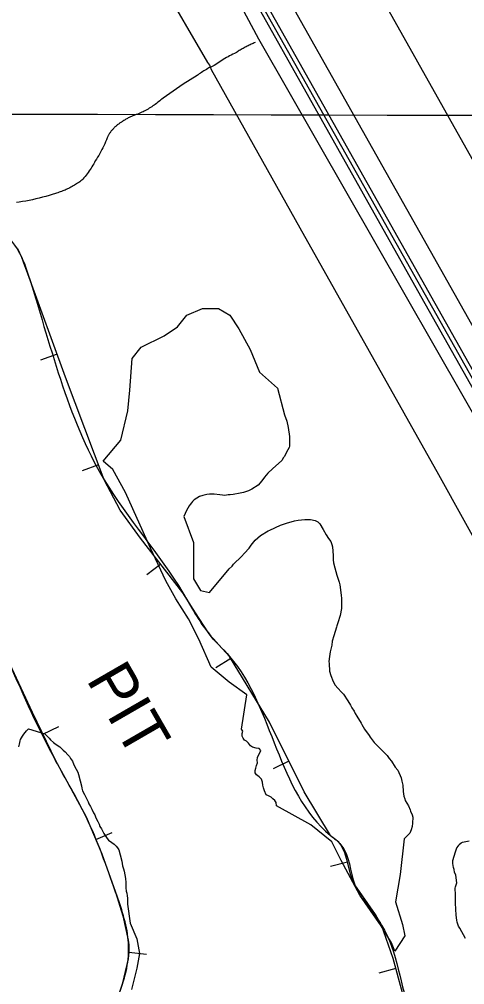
# Model space of a CAD drawing. Extents: x 3177185 to 3215018, y 812988 to 838321.
# Drawn here: x 3192464 to 3193094, y 823203 to 824566 of the extents above; entities that cross this region are included whole.
import ezdxf

# ---------------------------------------------------------------- set-up
doc = ezdxf.new("R2010")
doc.units = 0
for name, color, linetype in [('V-BORW-IDEN', 7, 'Continuous'), ('V-BORW-LINE', 7, 'Continuous'), ('V-GRID-MAJR', 7, 'Continuous'), ('V-LEVE-TOET', 7, 'Continuous'), ('V-RAIL-TRAK', 7, 'Continuous'), ('V-ROAD-CNTR', 7, 'Continuous'), ('V-SITE-VEGE', 7, 'Continuous'), ('V-SURV-LINE', 7, 'Continuous'), ('V-TOPO-SHOR', 7, 'Continuous')]:
    doc.layers.add(name, color=color, linetype=linetype)

msp = doc.modelspace()

# ---------------------------------------------------------------- linework, layer by layer
at = {"layer": 'V-BORW-LINE'}
for p, q in [((3192517.991, 824093.435), (3192494.512, 824084.848)), ((3192576.349, 823937.392), (3192552.949, 823928.591)), ((3192664.126, 823796.922), (3192644.37, 823781.6020000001)), ((3192763.312, 823663.634), (3192741.9620000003, 823650.628)), ((3192497.732, 823556.731), (3192520.272, 823567.547)), ((3192845.395, 823518.821), (3192823.012, 823507.685)), ((3192572.419, 823407.936), (3192595.392, 823417.797)), ((3192928.254, 823376.17), (3192904.069, 823369.841)), ((3192619.248, 823248.904), (3192644.08, 823246.006)), ((3192996.52, 823225.963), (3192972.395, 823219.404))]:
    msp.add_line(p, q, dxfattribs=at)
for points in [[(3193005.934, 823191.332), (3192992.722, 823239.931), (3192976.418, 823287.094), (3192967.948, 823301.838), (3192938.651, 823343.995), (3192933.0670000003, 823357.779), (3192927.286, 823379.8690000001), (3192923.827, 823390.643), (3192918.919, 823400.677), (3192915.682, 823404.332), (3192909.56, 823408.784), (3192906.61, 823411.094), (3192904.153, 823413.796), (3192866.96, 823475.476), (3192818.068, 823573.747), (3192761.5640000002, 823666.5040000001), (3192746.238, 823682.844), (3192738.419, 823690.924), (3192731.482, 823699.6780000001), (3192713.423, 823728.017), (3192695.518, 823756.439), (3192635.544, 823833.779), (3192606.807, 823873.113), (3192584.431, 823915.904), (3192529.812, 824061.117), (3192476.548, 824206.74), (3192472.168, 824218.468), (3192467.754, 824230.1900000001), (3192462.112, 824242.243)], [(3192337.378, 823940.962), (3192394.177, 823799.838), (3192450.6750000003, 823656.781), (3192482.6950000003, 823588.069), (3192515.512, 823519.68), (3192537.107, 823479.862), (3192558.6750000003, 823439.9550000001), (3192581.161, 823387.567), (3192600.502, 823333.666), (3192610.71, 823300.028), (3192618.286, 823265.887), (3192619.163, 823259.2980000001), (3192619.292, 823249.2760000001), (3192618.13, 823239.322), (3192609.906, 823203.8520000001), (3192603.901, 823186.684)]]:
    msp.add_lwpolyline(points, dxfattribs=at)
msp.add_spline([(3192337.378, 823940.962), (3192450.6750000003, 823656.781), (3192515.512, 823519.68), (3192558.6750000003, 823439.9550000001), (3192600.502, 823333.666), (3192618.286, 823265.887), (3192618.13, 823239.322), (3192596.168, 823170.181), (3192570.128, 823124.488), (3192544.017, 823075.534), (3192525.992, 822981.143), (3192537.224, 822863.983), (3192568.707, 822741.261), (3192590.757, 822730.8420000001), (3192607.4760000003, 822734.716), (3192633.424, 822744.133), (3192790.951, 822860.632), (3192848.333, 822890.561), (3193002.452, 822993.536), (3193064.424, 823044.062), (3193073.036, 823061.536), (3193065.488, 823079.991), (3193018.025, 823160.412), (3192976.418, 823287.094), (3192938.651, 823343.995), (3192918.919, 823400.677), (3192904.153, 823413.796), (3192761.5640000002, 823666.5040000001), (3192731.482, 823699.6780000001), (3192695.518, 823756.439), (3192584.431, 823915.904), (3192476.548, 824206.74), (3192467.754, 824230.1900000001), (3192433.582, 824267.9450000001), (3192365.528, 824253.63), (3192313.008, 824232.577), (3192261.659, 824199.732), (3192232.149, 824151.405), (3192237.406, 824127.957), (3192259.282, 824060.314), (3192337.378, 823940.962)], degree=3, dxfattribs=at)
at = {"layer": 'V-GRID-MAJR'}
msp.add_spline([(3181368.912, 824461.486), (3186603.869, 824447.399), (3191838.828, 824434.0750000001), (3197073.789, 824421.511), (3202308.752, 824409.709), (3207543.717, 824398.669), (3212778.683, 824388.39), (3212778.684, 824388.39)], degree=3, dxfattribs=at)
at = {"layer": 'V-LEVE-TOET'}
for points in [[(3192443.9620000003, 825569.056), (3192576.759, 825332.2270000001), (3192715.666, 825063.0530000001), (3192905.627, 824722.775), (3193107.897, 824362.329), (3193312.2770000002, 824000.415), (3193506.598, 823644.858), (3193758.434, 823202.424)], [(3193584.328, 822982.905), (3193407.808, 823299.272), (3193245.38, 823590.751), (3193227.242, 823622.956), (3193224.488, 823626.536), (3193223.0300000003, 823629.301), (3193219.786, 823632.719), (3193193.3850000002, 823677.941), (3193057.193, 823923.224), (3192861.4, 824271.31), (3192736.054, 824495.2880000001), (3192734.436, 824499.027), (3192733.627, 824501.466), (3192730.5470000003, 824505.536), (3192598.062, 824733.751), (3192434.161, 825019.219)]]:
    msp.add_lwpolyline(points, dxfattribs=at)
at = {"layer": 'V-RAIL-TRAK'}
msp.add_lwpolyline([(3193727.307, 822943), (3193577.661, 823206.018), (3193415.878, 823494.571), (3193219.921, 823842.66), (3193027.524, 824182.939), (3192797.072, 824592.348), (3192558.2, 825016.721), (3192352.2, 825381.723), (3192184.2600000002, 825679.875), (3191974.37, 826050.574), (3191871.696, 826233.868)], dxfattribs=at)
at = {"layer": 'V-ROAD-CNTR'}
msp.add_lwpolyline([(3191892.325178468, 826207.063558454), (3193654.2206546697, 823085.5218015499)], dxfattribs=at)
at = {"layer": 'V-SITE-VEGE'}
for p, q in [((3192474.594, 823561.301), (3192477.433, 823564.13)), ((3192477.433, 823564.13), (3192500.575, 823557.324)), ((3192466.075, 823549.177), (3192468.917, 823554.029)), ((3192468.917, 823554.029), (3192470.9450000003, 823556.857)), ((3192470.9450000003, 823556.857), (3192474.594, 823561.301)), ((3192500.575, 823557.324), (3192506.529, 823551.35)), ((3192506.529, 823551.35), (3192508.5130000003, 823548.96)), ((3192463.627, 823539.066), (3192464.444, 823542.707)), ((3192464.444, 823542.707), (3192464.8540000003, 823545.134)), ((3192464.8540000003, 823545.134), (3192465.665, 823547.156)), ((3192465.665, 823547.156), (3192466.075, 823549.177)), ((3192508.5130000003, 823548.96), (3192512.482, 823544.9770000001)), ((3192512.482, 823544.9770000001), (3192516.451, 823542.185)), ((3192516.451, 823542.185), (3192521.616, 823538.9940000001)), ((3192521.616, 823538.9940000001), (3192526.378, 823534.216)), ((3192526.378, 823534.216), (3192529.157, 823531.822)), ((3192529.157, 823531.822), (3192532.727, 823527.444)), ((3192532.727, 823527.444), (3192535.109, 823525.052)), ((3192535.109, 823525.052), (3192536.694, 823522.2660000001)), ((3192536.694, 823522.2660000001), (3192539.471, 823518.682)), ((3192539.471, 823518.682), (3192541.449, 823513.509)), ((3192541.449, 823513.509), (3192544.617, 823507.142)), ((3192544.617, 823507.142), (3192546.995, 823503.161)), ((3192546.995, 823503.161), (3192548.183, 823499.581)), ((3192548.183, 823499.581), (3192550.153, 823490.8300000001)), ((3192550.153, 823490.8300000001), (3192552.127, 823483.6680000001)), ((3192552.127, 823483.6680000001), (3192552.918, 823480.485)), ((3192552.918, 823480.485), (3192553.7060000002, 823476.905)), ((3192553.7060000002, 823476.905), (3192556.4790000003, 823471.732)), ((3192556.4790000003, 823471.732), (3192559.252, 823465.762)), ((3192559.252, 823465.762), (3192561.628, 823460.9860000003)), ((3192561.628, 823460.9860000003), (3192562.818, 823458.201)), ((3192562.818, 823458.201), (3192564.798, 823454.6190000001)), ((3192564.798, 823454.6190000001), (3192566.779, 823450.638)), ((3192566.779, 823450.638), (3192569.1550000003, 823445.8640000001)), ((3192569.1550000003, 823445.8640000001), (3192571.137, 823442.677)), ((3192571.137, 823442.677), (3192572.72, 823438.702)), ((3192572.72, 823438.702), (3192575.4930000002, 823433.524)), ((3192575.4930000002, 823433.524), (3192577.078, 823429.5430000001)), ((3192577.078, 823429.5430000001), (3192578.264, 823426.363)), ((3192578.264, 823426.363), (3192580.644, 823423.1780000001)), ((3192580.644, 823423.1780000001), (3192582.227, 823419.199)), ((3192582.227, 823419.199), (3192583.812, 823416.411)), ((3192583.812, 823416.411), (3192586.5870000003, 823412.033)), ((3192586.5870000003, 823412.033), (3192588.572, 823409.643)), ((3192588.572, 823409.643), (3192590.554, 823407.253)), ((3192590.554, 823407.253), (3192595.3200000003, 823403.667)), ((3192595.3200000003, 823403.667), (3192598.4960000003, 823401.277)), ((3192598.4960000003, 823401.277), (3192601.271, 823398.485)), ((3192601.271, 823398.485), (3192603.258, 823396.095)), ((3192603.258, 823396.095), (3192604.843, 823393.31)), ((3192604.843, 823393.31), (3192606.821, 823386.5470000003)), ((3192606.821, 823386.5470000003), (3192609.187, 823377.397)), ((3192609.187, 823377.397), (3192610.366, 823370.634)), ((3192610.366, 823370.634), (3192611.552, 823366.657)), ((3192611.552, 823366.657), (3192612.341, 823363.077)), ((3192612.341, 823363.077), (3192613.524, 823358.306)), ((3192613.524, 823358.306), (3192614.311, 823353.132)), ((3192614.311, 823353.132), (3192614.698, 823347.169)), ((3192614.698, 823347.169), (3192615.0870000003, 823342.794)), ((3192615.0870000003, 823342.794), (3192615.079, 823339.611)), ((3192615.079, 823339.611), (3192615.47, 823335.2390000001)), ((3192615.47, 823335.2390000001), (3192616.259, 823332.054)), ((3192616.259, 823332.054), (3192616.65, 823328.476)), ((3192616.65, 823328.476), (3192617.44, 823325.294)), ((3192617.434, 823322.113), (3192617.424, 823316.547)), ((3192617.44, 823325.294), (3192617.434, 823322.113)), ((3192617.424, 823316.547), (3192621.0840000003, 823290.046)), ((3192621.0840000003, 823290.046), (3192630.461, 823267.524)), ((3192630.461, 823267.524), (3192634.213, 823246.88)), ((3192634.213, 823246.88), (3192630.461, 823226.238)), ((3192630.461, 823226.238), (3192622.96, 823196.21))]:
    msp.add_line(p, q, dxfattribs=at)
for points in [[(3192688.09, 824132.318), (3192700.927, 824148.373), (3192723.3910000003, 824158), (3192745.856, 824158), (3192761.9, 824148.373), (3192774.741, 824129.107), (3192790.785, 824100.214), (3192803.622, 824068.108), (3192829.294, 824045.635), (3192839.218, 824007.767)], [(3192928.701, 823603.75), (3192932.33, 823597.676), (3192934.348, 823594.028), (3192937.575, 823589.166), (3192939.187, 823585.926), (3192941.204, 823582.281), (3192947.256, 823572.154), (3192948.467, 823570.532), (3192952.096, 823563.6460000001), (3192958.9590000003, 823554.733), (3192960.169, 823552.706), (3192965.819, 823545.005), (3192983.995, 823526.764), (3192987.223, 823522.305), (3192990.455, 823518.658), (3192995.7, 823510.148), (3192999.333, 823505.692), (3193003.765, 823495.1630000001), (3193004.5700000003, 823492.732), (3193004.969, 823490.3030000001), (3193006.171, 823484.636), (3193006.966, 823475.734), (3193007.762, 823469.258), (3193008.969, 823465.207), (3193009.774, 823463.182), (3193014.2120000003, 823455.487), (3193016.628, 823449.816), (3193017.0300000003, 823447.7930000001), (3193019.448, 823442.933), (3193020.251, 823439.693), (3193020.235, 823431.196), (3193019.416, 823426.3420000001), (3193018.193, 823421.488), (3193016.9760000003, 823419.4670000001), (3193016.161, 823417.04), (3193008.053, 823408.963), (3193002.589, 823358.582), (3192996.173, 823320.055), (3193005.8000000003, 823287.951), (3193009.012, 823271.898), (3192995.11, 823250.198), (3192990.563, 823261.8960000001), (3192975.56, 823286.29), (3192945.5500000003, 823329.451), (3192919.293, 823378.245), (3192906.163, 823404.519), (3192876.156, 823428.914), (3192828.024, 823455.7170000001), (3192827.237, 823460.488), (3192825.257, 823462.878), (3192822.4760000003, 823465.6680000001), (3192820.094, 823467.661), (3192816.5160000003, 823469.655), (3192813.342, 823471.251), (3192810.966, 823476.821), (3192809.3850000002, 823481.2000000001), (3192808.594, 823484.78), (3192808.205, 823488.757), (3192806.622, 823493.134), (3192803.448, 823496.3200000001), (3192799.477, 823499.11), (3192797.494, 823502.294), (3192797.5, 823505.4770000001), (3192798.698, 823508.655), (3192799.501, 823512.628), (3192801.099, 823516.202), (3192800.71, 823520.181), (3192801.113, 823523.759), (3192802.311, 823526.938), (3192804.308, 823530.514), (3192805.506, 823533.692), (3192803.524, 823536.479), (3192799.149, 823536.885), (3192793.984, 823538.484), (3192791.205, 823540.479), (3192788.426, 823544.061), (3192785.649, 823546.851), (3192782.47, 823548.448), (3192780.488, 823551.233), (3192779.304, 823554.019), (3192779.308, 823557.598), (3192780.109, 823561.174), (3192778.126, 823563.962), (3192785.708, 823612.2490000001), (3192760.696, 823630.1240000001), (3192735.686, 823651.5750000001), (3192717.823, 823690.9010000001), (3192703.5300000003, 823719.4990000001), (3192685.667, 823748.099), (3192671.374, 823773.1240000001), (3192649.938, 823819.5970000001), (3192614.208, 823898.248), (3192596.344, 823930.425), (3192583.015, 823942.278), (3192607.862, 823971.792), (3192617.487, 824013.528), (3192620.697, 824042.424), (3192623.906, 824087.371), (3192636.7430000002, 824103.4230000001), (3192668.835, 824119.4770000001), (3192688.09, 824132.318)], [(3192839.218, 824007.767), (3192842.438, 823998.858), (3192844.4450000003, 823989.952), (3192846.042, 823977), (3192846.0130000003, 823963.645), (3192845.606, 823961.6240000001), (3192843.982, 823958.39), (3192839.921, 823951.113), (3192839.108, 823949.0920000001), (3192837.8910000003, 823947.474), (3192835.4560000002, 823943.433), (3192822.078, 823931.3200000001), (3192815.592, 823925.262), (3192810.7260000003, 823919.605), (3192807.077, 823914.757), (3192801.803, 823908.6950000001), (3192792.89, 823903.047), (3192788.436, 823900.628), (3192785.196, 823899.42), (3192781.147, 823898.214), (3192776.291, 823897.007), (3192766.574, 823895.408), (3192762.5270000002, 823894.605), (3192759.289, 823894.611), (3192754.836, 823893.81), (3192751.6010000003, 823894.2220000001), (3192747.554, 823895.039), (3192739.8680000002, 823895.863), (3192732.988, 823895.875), (3192729.345, 823895.4770000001), (3192723.676, 823893.87), (3192719.224, 823892.258), (3192711.525, 823887.822), (3192709.094, 823885.399), (3192707.47, 823883.38), (3192705.848, 823880.953), (3192704.2260000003, 823879.337), (3192700.573, 823872.466), (3192698.944, 823868.421), (3192696.915, 823864.381), (3192710.555, 823827.318), (3192710.555, 823798.427), (3192710.555, 823775.9500000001), (3192720.182, 823759.8960000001), (3192733.019, 823756.687), (3192761.116, 823790.206), (3192765.171, 823794.247), (3192767.198, 823796.67), (3192778.145, 823807.5750000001), (3192782.605, 823812.4230000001), (3192789.093, 823819.6950000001), (3192791.934, 823823.736), (3192797.613, 823831.009), (3192805.313, 823837.47), (3192816.248, 823843.9230000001), (3192818.275, 823844.728), (3192833.666, 823851.982), (3192841.764, 823854.802), (3192853.102, 823858.018), (3192858.363, 823858.816), (3192868.076, 823860.012), (3192875.765, 823860), (3192882.642, 823858.7710000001), (3192886.279, 823856.742), (3192889.107, 823853.903), (3192893.949, 823845.801), (3192897.9790000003, 823838.105), (3192901.207, 823833.245), (3192904.437, 823828.786), (3192906.048, 823824.738), (3192906.8510000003, 823821.498), (3192908.041, 823808.954), (3192908.031, 823802.881), (3192908.428, 823798.834), (3192910.034, 823791.5480000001), (3192912.848, 823781.426), (3192916.471, 823771.301), (3192917.272, 823767.66), (3192918.068, 823760.778), (3192919.2660000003, 823752.683), (3192919.666, 823749.039), (3192919.639, 823734.474), (3192918.001, 823724.359), (3192914.339, 823713.844), (3192913.116, 823709.802), (3192912.7090000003, 823707.778), (3192908.639, 823695.6460000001), (3192906.6010000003, 823687.962), (3192905.782, 823682.297), (3192903.74, 823672.993), (3192902.5160000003, 823666.5210000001), (3192901.6920000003, 823659.644), (3192902.092, 823656.406), (3192902.88, 823645.884), (3192904.49, 823639.811), (3192908.115, 823631.306), (3192910.937, 823626.041), (3192914.5700000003, 823621.582), (3192919.821, 823616.313), (3192922.648, 823613.071), (3192928.701, 823603.75)], [(3193094.792, 823268.384), (3193087.131, 823282.558), (3193085.113, 823285.802), (3193083.1, 823291.068), (3193082.701, 823293.9), (3193081.904, 823301.185), (3193080.722, 823318.183), (3193080.745, 823329.9180000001), (3193080.358, 823339.226), (3193080.765, 823341.25), (3193082.799, 823346.91), (3193081.202, 823357.839), (3193079.59, 823361.887), (3193078.787, 823365.533), (3193077.986, 823368.365), (3193077.185, 823374.032), (3193077.194, 823378.484), (3193080.858, 823390.617), (3193082.8910000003, 823396.277), (3193084.921, 823399.108), (3193086.137, 823401.125), (3193088.572, 823403.1460000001), (3193090.596, 823404.357), (3193099.906, 823405.958)]]:
    msp.add_lwpolyline(points, dxfattribs=at)
at = {"layer": 'V-SURV-LINE'}
for points in [[(3192530.8513585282, 825151.2019599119), (3193991.2674724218, 822560.8461892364)], [(3193965.131375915, 822546.1185111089), (3192504.7150828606, 825136.4745995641)]]:
    msp.add_lwpolyline(points, dxfattribs=at)
at = {"layer": 'V-TOPO-SHOR'}
for points in [[(3195564.015249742, 819660.7407383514), (3195052.0819714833, 820581.0702273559), (3194839.255777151, 820937.6979043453), (3194281.0270000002, 821921.388), (3194056.975711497, 822346.9524343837), (3193780.876864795, 822818.6212974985), (3193257.439467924, 823744.7028458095), (3192803.0267827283, 824538.4870300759), (3192509.671758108, 825084.9326641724), (3192365.870275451, 825332.2712143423), (3191974.730242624, 826039.7745090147)], [(3192797.541, 824533.608), (3192796.1180000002, 824533.032), (3192794.6950000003, 824532.436), (3192793.273, 824531.822), (3192791.8540000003, 824531.189), (3192790.4390000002, 824530.536), (3192789.024, 824529.866), (3192787.615, 824529.176), (3192786.21, 824528.469), (3192784.807, 824527.7440000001), (3192783.412, 824527.001), (3192782.02, 824526.241), (3192780.6350000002, 824525.463), (3192779.255, 824524.6680000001), (3192777.883, 824523.855), (3192776.517, 824523.028), (3192775.157, 824522.182), (3192773.805, 824521.322), (3192772.464, 824520.4450000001), (3192771.128, 824519.552), (3192770.577, 824519.177), (3192768.296, 824518.1190000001), (3192766.025, 824517.025), (3192763.768, 824515.897), (3192761.521, 824514.733), (3192759.287, 824513.537), (3192757.0670000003, 824512.306), (3192754.861, 824511.045), (3192752.67, 824509.751), (3192750.4930000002, 824508.4230000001), (3192748.3340000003, 824507.066), (3192746.1920000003, 824505.675), (3192744.066, 824504.2540000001), (3192741.9590000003, 824502.802), (3192739.872, 824501.321), (3192739.732, 824501.221), (3192739.732, 824501.221), (3192737.879, 824500.395), (3192736.038, 824499.537), (3192734.213, 824498.6460000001), (3192732.403, 824497.725), (3192730.609, 824496.77), (3192728.8310000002, 824495.787), (3192727.0700000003, 824494.7710000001), (3192725.325, 824493.7270000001), (3192723.598, 824492.652), (3192721.89, 824491.5480000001), (3192720.203, 824490.4130000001), (3192718.532, 824489.25), (3192716.883, 824488.058), (3192715.63, 824487.122), (3192715.63, 824487.122), (3192705.811, 824481.054), (3192696.098, 824474.816), (3192686.486, 824468.414), (3192676.984, 824461.848), (3192667.594, 824455.12), (3192665.9, 824453.8790000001), (3192664.37, 824452.56), (3192662.8200000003, 824451.2660000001), (3192661.251, 824449.996), (3192659.66, 824448.753), (3192658.052, 824447.534), (3192656.426, 824446.344), (3192654.781, 824445.179), (3192653.1180000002, 824444.04), (3192651.4390000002, 824442.93), (3192649.7430000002, 824441.849), (3192648.031, 824440.794), (3192646.303, 824439.768), (3192644.56, 824438.7710000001), (3192642.803, 824437.802), (3192641.0330000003, 824436.8640000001), (3192639.247, 824435.9550000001), (3192637.451, 824435.076), (3192635.6410000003, 824434.226), (3192633.8200000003, 824433.407), (3192631.989, 824432.6190000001), (3192631.85, 824432.561), (3192630.6890000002, 824432.201), (3192629.534, 824431.824), (3192628.383, 824431.429), (3192627.236, 824431.015), (3192626.095, 824430.583), (3192624.96, 824430.132), (3192623.832, 824429.666), (3192622.71, 824429.18), (3192621.594, 824428.6780000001), (3192620.484, 824428.158), (3192619.382, 824427.622), (3192618.288, 824427.067), (3192617.203, 824426.495), (3192616.125, 824425.909), (3192615.058, 824425.305), (3192613.998, 824424.685), (3192612.947, 824424.0480000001), (3192611.907, 824423.397), (3192610.876, 824422.729), (3192610.278, 824422.332), (3192609.416, 824421.8200000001), (3192608.56, 824421.295)], [(3192608.56, 824421.295), (3192607.716, 824420.755), (3192606.881, 824420.2000000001), (3192606.055, 824419.63), (3192605.238, 824419.047), (3192604.433, 824418.449), (3192603.639, 824417.836), (3192602.8540000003, 824417.212), (3192602.08, 824416.573), (3192601.3200000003, 824415.919), (3192600.569, 824415.2540000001), (3192599.832, 824414.576), (3192599.1040000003, 824413.884), (3192598.39, 824413.179), (3192597.687, 824412.462), (3192596.999, 824411.735), (3192596.321, 824410.9940000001), (3192595.6580000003, 824410.242), (3192595.008, 824409.478), (3192594.372, 824408.704), (3192593.747, 824407.92), (3192593.139, 824407.123), (3192592.543, 824406.316), (3192591.961, 824405.4990000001), (3192591.394, 824404.672), (3192590.843, 824403.836), (3192590.304, 824402.99), (3192589.782, 824402.134), (3192589.7, 824401.997), (3192589.7, 824401.997), (3192588.6040000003, 824399.134), (3192587.4620000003, 824396.289), (3192586.268, 824393.465), (3192585.0270000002, 824390.659), (3192583.738, 824387.876), (3192582.403, 824385.115), (3192581.021, 824382.375), (3192579.591, 824379.662), (3192578.117, 824376.97), (3192576.595, 824374.304), (3192575.028, 824371.666), (3192573.418, 824369.0530000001), (3192571.786, 824366.505), (3192571.786, 824366.505), (3192570.639, 824364.4), (3192569.458, 824362.313), (3192568.237, 824360.2490000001), (3192566.982, 824358.207), (3192565.691, 824356.185), (3192564.366, 824354.189), (3192563.006, 824352.214), (3192561.614, 824350.263), (3192560.186, 824348.337), (3192558.7260000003, 824346.437), (3192557.231, 824344.561), (3192555.705, 824342.712), (3192554.149, 824340.8910000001), (3192552.711, 824339.265), (3192552.711, 824339.265), (3192551.255, 824338.149), (3192549.7800000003, 824337.059), (3192548.287, 824335.9940000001), (3192546.776, 824334.956), (3192545.2460000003, 824333.942), (3192543.7, 824332.957), (3192542.1350000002, 824332.001), (3192540.554, 824331.069), (3192538.957, 824330.165), (3192537.345, 824329.291), (3192535.719, 824328.4450000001), (3192534.076, 824327.626), (3192532.4220000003, 824326.837), (3192530.752, 824326.078), (3192529.071, 824325.3470000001), (3192527.375, 824324.644), (3192525.669, 824323.9720000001), (3192523.951, 824323.331), (3192522.223, 824322.719), (3192520.482, 824322.137), (3192518.733, 824321.586), (3192516.974, 824321.066), (3192515.466, 824320.6460000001), (3192510.928, 824319.123), (3192506.363, 824317.677), (3192501.773, 824316.311), (3192497.159, 824315.027), (3192492.524, 824313.8200000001), (3192487.869, 824312.696), (3192483.196, 824311.654), (3192478.504, 824310.691), (3192473.798, 824309.81), (3192469.075, 824309.014), (3192464.34, 824308.297), (3192460.555, 824307.785)]]:
    msp.add_lwpolyline(points, dxfattribs=at)

# ---------------------------------------------------------------- texts
at = {"layer": 'V-BORW-IDEN'}
msp.add_text('PIT', height=64.00000199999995, rotation=299.98166000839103, dxfattribs=at).set_placement((3192558.215956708, 823634.0300823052))

doc.saveas('drawing.dxf')
